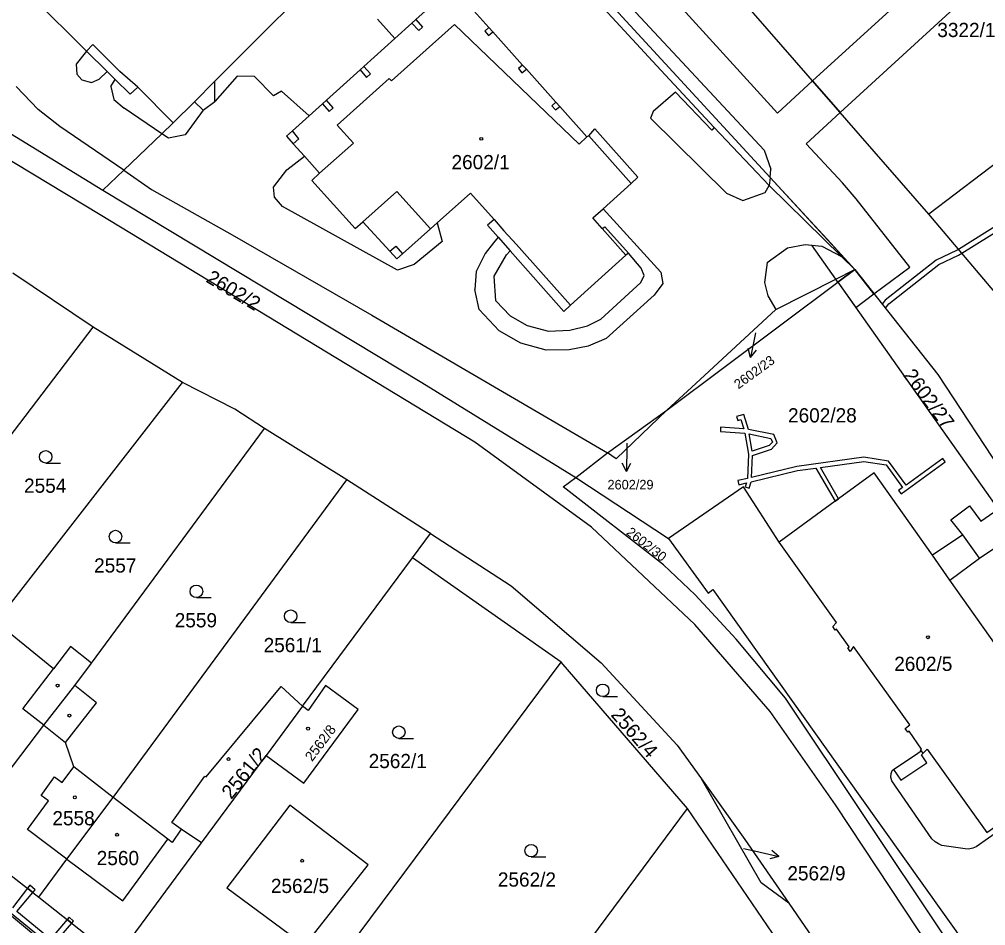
# Model space of a CAD drawing. Extents: x -869103 to -863415, y -1015889 to -1012477.
# Drawn here: x -866718.3 to -866602.7, y -1014593.6 to -1014485.3 of the extents above; entities that cross this region are included whole.
import ezdxf

# ---------------------------------------------------------------- set-up
doc = ezdxf.new("R2010")
doc.units = 0
for name, color, linetype in [('Hranice parcel', 7, 'Continuous'), ('Parcelní čísla', 7, 'Continuous'), ('Pop  PČ popisy', 7, 'Continuous'), ('Vnitřní kresba', 7, 'Continuous'), ('Věcná břemena k části', 7, 'Continuous'), ('Značky budov', 7, 'Continuous'), ('Značky kultur', 7, 'Continuous')]:
    doc.layers.add(name, color=color, linetype=linetype)

msp = doc.modelspace()

# ---------------------------------------------------------------- linework, layer by layer
at = {"layer": 'Hranice parcel'}
for p, q in [((-866708.59, -1014508.68), (-866764.02, -1014475.23)), ((-866609.5, -1014508.59), (-866632.45, -1014482.24)), ((-866738.67, -1014487.04), (-866708.25, -1014505.73)), ((-866590.37, -1014494.07), (-866609.5, -1014508.59)), ((-866709.44, -1014522.08), (-866719.05, -1014515.64)), ((-866620.38, -1014516.71), (-866618.35, -1014515.19)), ((-866640.82, -1014532.02), (-866620.38, -1014516.71)), ((-866620.38, -1014516.71), (-866601.19, -1014543.84)), ((-866727.94, -1014546.36), (-866709.44, -1014522.08)), ((-866698.76, -1014528.7), (-866709.44, -1014522.08)), ((-866721.06, -1014557.37), (-866698.76, -1014528.7)), ((-866640.82, -1014532.02), (-866637.36, -1014528.82)), ((-866647.92, -1014537.12), (-866640.82, -1014532.02)), ((-866640.82, -1014532.02), (-866646.87, -1014537.84)), ((-866709.64, -1014562.25), (-866688.95, -1014534.21)), ((-866679.11, -1014540.36), (-866688.95, -1014534.21)), ((-866651.72, -1014540.05), (-866647.92, -1014537.12)), ((-866646.87, -1014537.84), (-866647.92, -1014537.12)), ((-866707.05, -1014578.31), (-866679.11, -1014540.36)), ((-866669.09, -1014546.76), (-866679.11, -1014540.36)), ((-866651.72, -1014540.05), (-866640.61, -1014547.37)), ((-866671.24, -1014549.67), (-866669.09, -1014546.76)), ((-866684.38, -1014567.41), (-866671.24, -1014549.67)), ((-866653.45, -1014562.13), (-866671.24, -1014549.67)), ((-866711.63, -1014564.95), (-866709.64, -1014562.25)), ((-866689.69, -1014610.8), (-866653.45, -1014562.13)), ((-866638.35, -1014579.62), (-866653.45, -1014562.13)), ((-866684.38, -1014567.41), (-866688.73, -1014573.29)), ((-866696.48, -1014583.73), (-866688.73, -1014573.29)), ((-866671.71, -1014624.55), (-866638.35, -1014579.62)), ((-866620.29, -1014606.11), (-866638.35, -1014579.62)), ((-866725.35, -1014582.87), (-866715.91, -1014590.24)), ((-866696.48, -1014583.73), (-866698.89, -1014582.09)), ((-866709.06, -1014600.88), (-866723.33, -1014589.08)), ((-866715.91, -1014590.24), (-866706.66, -1014597.56))]:
    msp.add_line(p, q, dxfattribs=at)
for points in [[(-866665.72, -1014463.71), (-866659.64, -1014470.32), (-866628.47, -1014504.19), (-866618.35, -1014515.19)], [(-866708.25, -1014505.73), (-866705.77, -1014503.34), (-866701.2, -1014498.96), (-866699.84, -1014497.65), (-866697.32, -1014495.14), (-866694.87, -1014492.69), (-866689.96, -1014487.78), (-866684.34, -1014482.16), (-866682.19, -1014480.02), (-866671.3, -1014469.23), (-866670.82, -1014468.75), (-866669.45, -1014467.39), (-866669.11, -1014467.06)], [(-866669.11, -1014467.06), (-866667.36, -1014468.8), (-866655.19, -1014476.6), (-866641.53, -1014491.36), (-866635.15, -1014498.22), (-866628.58, -1014505.17), (-866619.92, -1014513.64), (-866618.35, -1014515.19)], [(-866708.25, -1014505.73), (-866670.11, -1014528.69), (-866651.72, -1014540.05)], [(-866637.48, -1014557.65), (-866649.85, -1014546.01), (-866663.79, -1014535.84), (-866708.59, -1014508.68)], [(-866580.41, -1014546.83), (-866593.72, -1014527.22), (-866609.5, -1014508.59)], [(-866637.36, -1014528.82), (-866627.8, -1014519.97), (-866620.63, -1014516.35), (-866618.35, -1014515.19)], [(-866618.35, -1014515.19), (-866608.4, -1014527.76), (-866600.07, -1014540.41), (-866598.84, -1014542.22)], [(-866688.95, -1014534.21), (-866692.47, -1014531.9), (-866698.76, -1014528.7)], [(-866584.89, -1014629.47), (-866598.39, -1014608.78), (-866626.65, -1014566.46), (-866632.52, -1014559.39), (-866637.43, -1014554.11), (-866641.24, -1014550.52), (-866653.22, -1014541.2), (-866651.72, -1014540.05)], [(-866616.04, -1014539.5), (-866620.29, -1014542.6), (-866620.69, -1014542.9), (-866627.4, -1014547.8)], [(-866605.41, -1014546.93), (-866609.06, -1014549.36), (-866616.04, -1014539.5)], [(-866627.4, -1014547.8), (-866631.66, -1014541.2), (-866640.61, -1014547.37)], [(-866669.09, -1014546.76), (-866659.44, -1014553), (-866648.69, -1014562.24), (-866639.57, -1014572.08), (-866636.68, -1014576.11)], [(-866613.71, -1014574.97), (-866612.83, -1014576.25), (-866609.72, -1014574.19), (-866610.35, -1014573.21), (-866610.19, -1014573.08), (-866609.71, -1014572.53), (-866602.57, -1014582.51), (-866591.25, -1014574.52), (-866606.97, -1014552.32), (-866603.43, -1014549.72), (-866605.41, -1014546.93)], [(-866640.61, -1014547.37), (-866635.9, -1014553.9), (-866635.32, -1014553.45), (-866617.75, -1014578.17), (-866597.38, -1014606.72)], [(-866613.71, -1014574.97), (-866610.79, -1014573.03), (-866610.42, -1014572.76), (-866610.5, -1014572.64), (-866610.35, -1014572.53), (-866611.86, -1014570.41), (-866612.01, -1014570.52), (-866612.32, -1014570.09), (-866611.77, -1014569.65), (-866618.5, -1014560.25), (-866618.89, -1014560.86), (-866619.19, -1014560.43), (-866619.02, -1014560.31), (-866620.52, -1014558.19), (-866620.68, -1014558.3), (-866620.99, -1014557.86), (-866620.53, -1014557.41), (-866627.4, -1014547.8)], [(-866709.64, -1014562.25), (-866712.13, -1014560.27), (-866714.17, -1014562.93), (-866721.06, -1014557.37)], [(-866545.74, -1014697.95), (-866553.76, -1014682.22), (-866583.39, -1014635.82), (-866600.98, -1014608.95), (-866620.65, -1014579.2), (-866628.48, -1014568.04), (-866637.48, -1014557.65)], [(-866725.35, -1014582.87), (-866715.33, -1014569.69), (-866711.63, -1014564.95)], [(-866707.05, -1014578.31), (-866711.75, -1014574.66), (-866712.72, -1014571.73), (-866709.01, -1014566.99), (-866711.63, -1014564.95)], [(-866698.89, -1014582.09), (-866700.01, -1014581.33), (-866696.08, -1014575.77), (-866695.93, -1014575.87), (-866686.95, -1014565.05), (-866684.38, -1014567.41)], [(-866688.73, -1014573.29), (-866684.24, -1014576.61), (-866677.75, -1014567.81), (-866681.63, -1014564.95), (-866683.7, -1014567.93), (-866684.38, -1014567.41)], [(-866584.47, -1014569.12), (-866584.27, -1014569.52), (-866584.2, -1014570), (-866584.34, -1014570.4), (-866584.64, -1014570.76), (-866603.82, -1014584.22), (-866604.22, -1014584.37), (-866604.73, -1014584.51), (-866605.15, -1014584.47), (-866607.93, -1014584.05), (-866608.35, -1014583.88), (-866608.74, -1014583.63), (-866609.13, -1014583.26), (-866613.9, -1014576.32), (-866614.02, -1014575.9), (-866614.01, -1014575.46), (-866613.86, -1014575.11), (-866613.71, -1014574.97)], [(-866636.68, -1014576.11), (-866631.49, -1014583.34), (-866626.25, -1014590.97)], [(-866626.25, -1014590.97), (-866629.56, -1014588.53), (-866636.68, -1014576.11)], [(-866715.91, -1014590.24), (-866712.56, -1014585.68), (-866707.05, -1014578.31)], [(-866698.89, -1014582.09), (-866699.97, -1014583.69), (-866700.5, -1014583.29), (-866707.05, -1014578.31)], [(-866685.89, -1014579.24), (-866693.44, -1014589.13), (-866684.11, -1014596.03), (-866676.54, -1014586.37), (-866685.89, -1014579.24)], [(-866706.66, -1014597.56), (-866697.71, -1014585.4), (-866696.48, -1014583.73)], [(-866626.25, -1014590.97), (-866618.21, -1014602.65), (-866617.55, -1014603.69)]]:
    msp.add_lwpolyline(points, dxfattribs=at)
at = {"layer": 'Pop  PČ popisy'}
for p, q in [((-866630.23, -1014522.77), (-866630.8, -1014525.72)), ((-866630.23, -1014522.76), (-866630.23, -1014522.77)), ((-866630.8, -1014525.72), (-866631.1, -1014524.64)), ((-866630.8, -1014525.72), (-866630.12, -1014524.83)), ((-866645.61, -1014536.36), (-866645.66, -1014539.36)), ((-866645.6, -1014535.98), (-866645.61, -1014536.36)), ((-866645.66, -1014539.36), (-866646.15, -1014538.35)), ((-866645.66, -1014539.36), (-866645.14, -1014538.37)), ((-866631.64, -1014584.4), (-866630.33, -1014584.71)), ((-866630.33, -1014584.71), (-866627.41, -1014585.39)), ((-866627.41, -1014585.39), (-866628.49, -1014585.65)), ((-866627.41, -1014585.39), (-866628.27, -1014584.67))]:
    msp.add_line(p, q, dxfattribs=at)
at = {"layer": 'Vnitřní kresba'}
for p, q in [((-866655.1, -1014473.09), (-866639.55, -1014489.81)), ((-866717.87, -1014481.41), (-866710.21, -1014489.09)), ((-866666.97, -1014481.84), (-866670.83, -1014485.32)), ((-866662.1, -1014486.28), (-866665.65, -1014482.31)), ((-866675.42, -1014485.26), (-866673.34, -1014487.58)), ((-866666.22, -1014485.91), (-866673.75, -1014492.64)), ((-866671.31, -1014485.75), (-866673.34, -1014487.58)), ((-866670.83, -1014485.32), (-866671.31, -1014485.75)), ((-866670.5, -1014486.64), (-866671.31, -1014485.75)), ((-866670.83, -1014485.32), (-866670.03, -1014486.21)), ((-866651.29, -1014500.2), (-866666.22, -1014485.91)), ((-866670.03, -1014486.21), (-866670.5, -1014486.64)), ((-866662.1, -1014486.28), (-866662.6, -1014486.72)), ((-866662.6, -1014486.72), (-866662.15, -1014487.21)), ((-866662.15, -1014487.21), (-866661.62, -1014486.79)), ((-866661.62, -1014486.79), (-866662.1, -1014486.28)), ((-866658.07, -1014490.76), (-866661.62, -1014486.79)), ((-866709.45, -1014488.31), (-866710.21, -1014489.09)), ((-866707.01, -1014490.75), (-866709.45, -1014488.31)), ((-866677.05, -1014490.93), (-866673.34, -1014487.58)), ((-866710.21, -1014489.09), (-866711.44, -1014490.65)), ((-866710.21, -1014489.09), (-866707.77, -1014491.51)), ((-866711.44, -1014490.65), (-866711.37, -1014491.86)), ((-866639.55, -1014489.81), (-866629.2, -1014500.94)), ((-866708.72, -1014492.45), (-866707.77, -1014491.51)), ((-866707.77, -1014491.51), (-866706.8, -1014492.48)), ((-866706.24, -1014491.53), (-866707.01, -1014490.75)), ((-866704.1, -1014493.4), (-866706.24, -1014491.53)), ((-866681.53, -1014494.97), (-866677.49, -1014491.34)), ((-866677.49, -1014491.34), (-866677.05, -1014490.93)), ((-866677.49, -1014491.34), (-866676.73, -1014492.25)), ((-866676.25, -1014491.82), (-866677.05, -1014490.93)), ((-866676.73, -1014492.25), (-866676.25, -1014491.82)), ((-866658.07, -1014490.76), (-866658.58, -1014491.18)), ((-866658.58, -1014491.18), (-866658.15, -1014491.67)), ((-866658.15, -1014491.67), (-866657.62, -1014491.24)), ((-866657.62, -1014491.24), (-866658.07, -1014490.76)), ((-866654.09, -1014495.19), (-866657.62, -1014491.24)), ((-866711.37, -1014491.86), (-866710.79, -1014492.51)), ((-866710.79, -1014492.51), (-866709.64, -1014492.84)), ((-866709.64, -1014492.84), (-866708.72, -1014492.45)), ((-866707.3, -1014493.34), (-866706.8, -1014492.48)), ((-866706.8, -1014492.48), (-866705.01, -1014494.25)), ((-866694.86, -1014495.1), (-866694.87, -1014492.69)), ((-866692.2, -1014492.08), (-866694.86, -1014495.1)), ((-866690.12, -1014492.12), (-866692.2, -1014492.08)), ((-866687.84, -1014494.45), (-866690.12, -1014492.12)), ((-866674.04, -1014492.35), (-866680.23, -1014497.93)), ((-866673.75, -1014492.64), (-866674.04, -1014492.35)), ((-866715.99, -1014496.08), (-866718.64, -1014493.31)), ((-866707.3, -1014493.34), (-866706.95, -1014494.87)), ((-866705.01, -1014494.25), (-866704.1, -1014493.4)), ((-866704.1, -1014493.4), (-866699.84, -1014497.65)), ((-866686.89, -1014493.89), (-866687.84, -1014494.45)), ((-866683.61, -1014496.84), (-866686.89, -1014493.89)), ((-866639.77, -1014494), (-866642.47, -1014496.31)), ((-866635.46, -1014498.53), (-866639.77, -1014494)), ((-866706.95, -1014494.87), (-866705.73, -1014495.92)), ((-866697.32, -1014495.14), (-866696.29, -1014496.15)), ((-866696.29, -1014496.15), (-866694.86, -1014495.1)), ((-866682.01, -1014495.4), (-866681.53, -1014494.97)), ((-866680.73, -1014495.86), (-866681.53, -1014494.97)), ((-866654.09, -1014495.19), (-866654.59, -1014495.62)), ((-866653.61, -1014495.71), (-866654.09, -1014495.19)), ((-866713.42, -1014498.09), (-866715.99, -1014496.08)), ((-866701.2, -1014498.96), (-866705.73, -1014495.92)), ((-866696.29, -1014496.15), (-866698.42, -1014499.08)), ((-866683.61, -1014496.84), (-866682.01, -1014495.4)), ((-866682.01, -1014495.4), (-866681.21, -1014496.29)), ((-866681.21, -1014496.29), (-866680.73, -1014495.86)), ((-866654.59, -1014495.62), (-866654.14, -1014496.12)), ((-866654.14, -1014496.12), (-866653.61, -1014495.71)), ((-866650.37, -1014499.34), (-866653.61, -1014495.71)), ((-866642.47, -1014496.31), (-866642.77, -1014497.1)), ((-866683.61, -1014496.84), (-866685.57, -1014498.63)), ((-866642.77, -1014497.1), (-866633.68, -1014506.07)), ((-866705.77, -1014503.34), (-866713.42, -1014498.09)), ((-866685.57, -1014498.63), (-866686.31, -1014499.27)), ((-866684.83, -1014499.57), (-866685.57, -1014498.63)), ((-866680.23, -1014497.93), (-866678.31, -1014500.09)), ((-866650.15, -1014499.2), (-866649.45, -1014498.4)), ((-866644.31, -1014504.15), (-866649.45, -1014498.4)), ((-866635.15, -1014498.22), (-866635.46, -1014498.53)), ((-866700.42, -1014499.48), (-866701.2, -1014498.96)), ((-866698.42, -1014499.08), (-866700.42, -1014499.48)), ((-866686.31, -1014499.27), (-866685.5, -1014500.18)), ((-866685.5, -1014500.18), (-866684.83, -1014499.57)), ((-866650.37, -1014499.34), (-866651.29, -1014500.2)), ((-866650.15, -1014499.2), (-866650.37, -1014499.34)), ((-866645.1, -1014504.9), (-866650.15, -1014499.2)), ((-866685.5, -1014500.18), (-866684.17, -1014501.66)), ((-866678.31, -1014500.09), (-866682.35, -1014503.68)), ((-866629.2, -1014500.94), (-866628.37, -1014503.21)), ((-866686.28, -1014503.29), (-866684.17, -1014501.66)), ((-866684.17, -1014501.66), (-866682.35, -1014503.68)), ((-866705.77, -1014503.34), (-866702.44, -1014505.63)), ((-866687.84, -1014505.37), (-866686.28, -1014503.29)), ((-866628.47, -1014504.19), (-866628.37, -1014503.21)), ((-866682.35, -1014503.68), (-866683.29, -1014504.56)), ((-866644.31, -1014504.15), (-866645.1, -1014504.9)), ((-866628.47, -1014504.19), (-866628.58, -1014505.17)), ((-866702.44, -1014505.63), (-866692.81, -1014511.05)), ((-866687.74, -1014506.57), (-866687.84, -1014505.37)), ((-866683.29, -1014504.56), (-866678.09, -1014510.31)), ((-866645.1, -1014504.9), (-866648.45, -1014507.93)), ((-866629.06, -1014505.98), (-866628.58, -1014505.17)), ((-866686.78, -1014507.66), (-866687.74, -1014506.57)), ((-866677.17, -1014509.49), (-866673.1, -1014505.86)), ((-866673.1, -1014505.86), (-866669.09, -1014510.35)), ((-866668.29, -1014509.61), (-866664.32, -1014506.07)), ((-866664.32, -1014506.07), (-866661.49, -1014509.24)), ((-866633.68, -1014506.07), (-866631.72, -1014506.93)), ((-866631.72, -1014506.93), (-866629.06, -1014505.98)), ((-866673.02, -1014515.28), (-866686.78, -1014507.66)), ((-866649.68, -1014509.04), (-866648.45, -1014507.93)), ((-866648.45, -1014507.93), (-866641.55, -1014515.5)), ((-866648.54, -1014510.31), (-866649.68, -1014509.04)), ((-866678.09, -1014510.31), (-866677.17, -1014509.49)), ((-866677.17, -1014509.49), (-866673.94, -1014512.99)), ((-866669.09, -1014510.35), (-866668.29, -1014509.61)), ((-866668.29, -1014509.61), (-866667.7, -1014511.85)), ((-866661.49, -1014509.24), (-866662.28, -1014509.9)), ((-866662.28, -1014509.9), (-866660.99, -1014511.35)), ((-866661.49, -1014509.24), (-866660.31, -1014510.57)), ((-866648.54, -1014510.31), (-866648.25, -1014510.1)), ((-866645.71, -1014513.48), (-866648.54, -1014510.31)), ((-866648.25, -1014510.1), (-866645.41, -1014513.23)), ((-866692.81, -1014511.05), (-866676.12, -1014520.66)), ((-866672.43, -1014513.32), (-866669.09, -1014510.35)), ((-866660.99, -1014511.35), (-866661.57, -1014512.03)), ((-866660.99, -1014511.35), (-866659.55, -1014512.97)), ((-866660.31, -1014510.57), (-866658.8, -1014512.21)), ((-866673.94, -1014512.99), (-866673.23, -1014512.42)), ((-866673.23, -1014512.42), (-866672.43, -1014513.32)), ((-866667.7, -1014511.85), (-866671.05, -1014514.59)), ((-866661.57, -1014512.03), (-866662.54, -1014513.29)), ((-866658.8, -1014512.21), (-866652.33, -1014519.45)), ((-866628.84, -1014514.37), (-866626.39, -1014512.59)), ((-866626.39, -1014512.59), (-866624.3, -1014512.21)), ((-866624.3, -1014512.21), (-866623.5, -1014512.29)), ((-866620.63, -1014516.35), (-866623.5, -1014512.29)), ((-866623.5, -1014512.29), (-866622.3, -1014512.41)), ((-866622.3, -1014512.41), (-866619.92, -1014513.64)), ((-866673.94, -1014512.99), (-866673.11, -1014513.92)), ((-866673.11, -1014513.92), (-866672.43, -1014513.32)), ((-866662.54, -1014513.29), (-866663.62, -1014515.44)), ((-866661.47, -1014515.98), (-866660, -1014513.43)), ((-866660, -1014513.43), (-866659.55, -1014512.97)), ((-866659.55, -1014512.97), (-866653.13, -1014520.2)), ((-866652.33, -1014519.45), (-866645.71, -1014513.48)), ((-866645.41, -1014513.23), (-866645.71, -1014513.48)), ((-866643.88, -1014515.02), (-866645.41, -1014513.23)), ((-866671.05, -1014514.59), (-866673.02, -1014515.28)), ((-866628.84, -1014514.37), (-866629.14, -1014516.74)), ((-866663.62, -1014515.44), (-866663.78, -1014517.59)), ((-866661.29, -1014518.96), (-866661.47, -1014515.98)), ((-866643.92, -1014516.75), (-866643.55, -1014515.92)), ((-866643.55, -1014515.92), (-866643.88, -1014515.02)), ((-866641.55, -1014515.5), (-866641.32, -1014516.89)), ((-866648.73, -1014521.12), (-866643.92, -1014516.75)), ((-866641.32, -1014516.89), (-866642.33, -1014518.26)), ((-866629.14, -1014516.74), (-866628.76, -1014518.36)), ((-866620.38, -1014516.71), (-866620.63, -1014516.35)), ((-866663.26, -1014519.98), (-866663.78, -1014517.59)), ((-866642.33, -1014518.26), (-866648.07, -1014523.45)), ((-866628.76, -1014518.36), (-866627.8, -1014519.97)), ((-866661.29, -1014518.96), (-866659.57, -1014520.75)), ((-866652.33, -1014519.45), (-866653.13, -1014520.2)), ((-866676.12, -1014520.66), (-866647.92, -1014537.12)), ((-866660.86, -1014522.55), (-866663.26, -1014519.98)), ((-866659.57, -1014520.75), (-866657.53, -1014521.9)), ((-866650.31, -1014521.92), (-866648.73, -1014521.12)), ((-866658.3, -1014524), (-866660.86, -1014522.55)), ((-866657.53, -1014521.9), (-866654.98, -1014522.58)), ((-866654.98, -1014522.58), (-866652.42, -1014522.47)), ((-866652.42, -1014522.47), (-866650.31, -1014521.92)), ((-866655.26, -1014524.86), (-866658.3, -1014524)), ((-866648.07, -1014523.45), (-866650.25, -1014524.37)), ((-866652.52, -1014524.81), (-866655.26, -1014524.86)), ((-866650.25, -1014524.37), (-866652.52, -1014524.81)), ((-866603.43, -1014549.72), (-866599.12, -1014546.82)), ((-866606.97, -1014552.32), (-866609.06, -1014549.36)), ((-866715.33, -1014569.69), (-866712.72, -1014571.73)), ((-866610.42, -1014572.76), (-866610.19, -1014573.08)), ((-866713.13, -1014576.53), (-866711.75, -1014574.66)), ((-866715.63, -1014578.08), (-866714.04, -1014575.86)), ((-866714.04, -1014575.86), (-866713.13, -1014576.53)), ((-866714.75, -1014578.72), (-866715.63, -1014578.08)), ((-866717.28, -1014582.15), (-866714.75, -1014578.72)), ((-866712.56, -1014585.68), (-866717.28, -1014582.15)), ((-866705.86, -1014590.66), (-866700.5, -1014583.29)), ((-866712.56, -1014585.68), (-866705.86, -1014590.66))]:
    msp.add_line(p, q, dxfattribs=at)
for points in [[(-866605.41, -1014546.93), (-866606.88, -1014545.12), (-866604.62, -1014543.46), (-866603.28, -1014545.28), (-866601.19, -1014543.84)], [(-866715.33, -1014569.69), (-866717.85, -1014567.74), (-866714.17, -1014562.93)]]:
    msp.add_lwpolyline(points, dxfattribs=at)
at = {"layer": 'Věcná břemena k části'}
for points in [[(-866703.66, -1014429.79), (-866699.5, -1014433.5), (-866665.72, -1014463.71), (-866659.64, -1014470.32), (-866628.47, -1014504.19), (-866621.23, -1014512.06), (-866618.35, -1014515.19), (-866616.05, -1014518.09), (-866611.75, -1014514.91), (-866618.17, -1014506.74), (-866619.83, -1014504.82), (-866624.16, -1014500.16), (-866620.1, -1014496.41), (-866623.39, -1014492.64), (-866627.58, -1014496.49), (-866642.23, -1014480.42), (-866653.18, -1014468.26), (-866673.59, -1014450.78), (-866700.75, -1014426.8)], [(-866623.39, -1014492.64), (-866620.1, -1014496.41), (-866603.22, -1014480.95), (-866610.01, -1014470.91), (-866613.48, -1014473.52), (-866612.4, -1014474.93), (-866612.78, -1014475.22), (-866612.14, -1014476.06), (-866609.76, -1014480.2)], [(-866614.28, -1014519.3), (-866608.28, -1014514.6), (-866605.95, -1014513.48), (-866605.56, -1014513.24), (-866600.5, -1014510.08), (-866598.14, -1014508.6), (-866598.48, -1014508.12), (-866600.82, -1014509.58), (-866605.95, -1014512.79), (-866606.19, -1014512.94), (-866608.63, -1014514.1), (-866614.7, -1014518.86), (-866615.06, -1014519.35), (-866614.67, -1014519.83)], [(-866620.38, -1014516.71), (-866618.22, -1014519.76), (-866616.05, -1014518.09), (-866618.35, -1014515.19)], [(-866614.33, -1014538.1), (-866617.28, -1014537.65), (-866625.28, -1014538.75), (-866630.69, -1014540.05), (-866630.58, -1014537.44), (-866628.29, -1014536.66), (-866627.61, -1014535.93), (-866628.03, -1014534.93), (-866631.07, -1014534.31), (-866631.63, -1014532.52), (-866632.48, -1014532.76), (-866632.34, -1014533.24), (-866631.96, -1014533.14), (-866631.62, -1014534.24), (-866634.39, -1014534.06), (-866634.42, -1014534.56), (-866631.48, -1014534.75), (-866631.07, -1014537.27), (-866631.19, -1014540.17), (-866632.32, -1014540.44), (-866632.2, -1014540.93), (-866631.31, -1014540.71), (-866631.45, -1014541.19), (-866630.97, -1014541.33), (-866630.75, -1014540.58), (-866625.19, -1014539.24), (-866622.99, -1014538.94), (-866620.69, -1014542.9), (-866620.29, -1014542.6), (-866622.46, -1014538.87), (-866617.28, -1014538.15), (-866614.61, -1014538.56), (-866612.63, -1014541.26), (-866613.11, -1014541.61), (-866612.82, -1014542.02), (-866607.53, -1014538.19), (-866607.82, -1014537.78), (-866612.22, -1014540.97)], [(-866630.62, -1014536.93), (-866630.96, -1014534.86), (-866628.38, -1014535.4), (-866628.2, -1014535.83), (-866628.57, -1014536.22)], [(-866717.27, -1014589.18), (-866716.62, -1014589.69), (-866716.35, -1014589.37), (-866716.99, -1014588.82)], [(-866711.99, -1014593.34), (-866711.78, -1014593.09), (-866712.29, -1014592.61), (-866712.54, -1014592.91)]]:
    msp.add_lwpolyline(points, close=True, dxfattribs=at)
for points in [[(-866713.99, -1014595.68), (-866711.99, -1014593.34), (-866712.54, -1014592.91), (-866714.54, -1014595.24), (-866718.55, -1014591.94), (-866716.62, -1014589.69), (-866717.27, -1014589.18), (-866719.09, -1014591.51)], [(-866719.22, -1014592.17), (-866711.91, -1014598.14)]]:
    msp.add_lwpolyline(points, dxfattribs=at)
at = {"layer": 'Značky budov'}
for centre in [(-866663.02, -1014499.58), (-866609.6, -1014559.16), (-866713.68, -1014564.94), (-866712.26, -1014568.53), (-866683.72, -1014570.09), (-866693.24, -1014573.73), (-866711.62, -1014578.3), (-866706.57, -1014582.77), (-866684.43, -1014585.88)]:
    msp.add_circle(centre, 0.175, dxfattribs=at)
at = {"layer": 'Značky kultur'}
for p, q in [((-866715.1, -1014538.34), (-866713.35, -1014538.34)), ((-866706.76, -1014547.88), (-866705.01, -1014547.88)), ((-866697.08, -1014554.43), (-866695.33, -1014554.43)), ((-866685.8, -1014557.4), (-866684.05, -1014557.4)), ((-866648.49, -1014566.26), (-866646.74, -1014566.26)), ((-866672.87, -1014571.26), (-866671.12, -1014571.26)), ((-866657.05, -1014585.43), (-866655.3, -1014585.43))]:
    msp.add_line(p, q, dxfattribs=at)
for centre in [(-866715.1, -1014537.59), (-866706.76, -1014547.13), (-866697.08, -1014553.68), (-866685.8, -1014556.65), (-866648.49, -1014565.51), (-866672.87, -1014570.51), (-866657.05, -1014584.68)]:
    msp.add_circle(centre, 0.75, dxfattribs=at)

# ---------------------------------------------------------------- texts
at = {"layer": 'Parcelní čísla'}
for s, height, p in [('3322/1', 1.7, (-866608.48, -1014487.41)), ('2602/1', 1.7, (-866666.57, -1014503.21)), ('2602/28', 1.7, (-866626.33, -1014533.48)), ('2554', 1.7, (-866717.69, -1014541.89)), ('2602/29', 1.139, (-866647.92, -1014541.49)), ('2557', 1.7, (-866709.31, -1014551.43)), ('2559', 1.7, (-866699.67, -1014557.98)), ('2561/1', 1.7, (-866689.04, -1014560.95)), ('2602/5', 1.7, (-866613.63, -1014563.19)), ('2562/1', 1.7, (-866676.48, -1014574.81)), ('2558', 1.7, (-866714.3, -1014581.65)), ('2560', 1.7, (-866709, -1014586.41)), ('2562/9', 1.7, (-866626.41, -1014588.23)), ('2562/2', 1.7, (-866661.03, -1014588.98)), ('2562/5', 1.7, (-866688.17, -1014589.74))]:
    msp.add_text(s, height=height, dxfattribs=at).set_placement(p)
for s, height, rotation, p in [('2602/2', 1.7, 329, (-866696.04, -1014516.62)), ('2602/23', 1.139, 36, (-866632.26, -1014529.54)), ('2602/27', 1.7, 307, (-866612.62, -1014527.87)), ('2602/30', 1.139, 322, (-866645.76, -1014546.8)), ('2562/4', 1.7, 311, (-866647.6, -1014568.49)), ('2562/8', 1.19, 53, (-866683.24, -1014574.09)), ('2561/2', 1.7, 51, (-866692.9, -1014578.63))]:
    msp.add_text(s, height=height, rotation=rotation, dxfattribs=at).set_placement(p)

doc.saveas('drawing.dxf')
